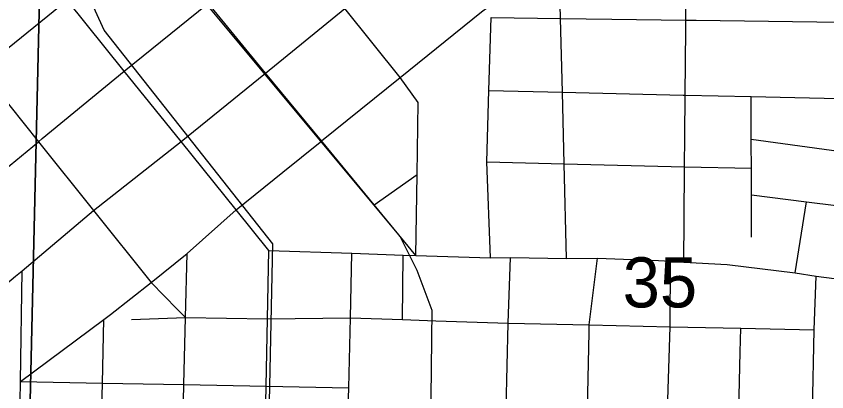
# Model space of a CAD drawing. Extents: x 0 to 68.9, y -26.1 to 22.
# Drawn here: x 5.236 to 5.914, y 17.27 to 17.583 of the extents above; entities that cross this region are included whole.
import ezdxf

# ---------------------------------------------------------------- set-up
doc = ezdxf.new("R2010")
doc.units = 0
for name, color, linetype in [('GM_X_City_Street', 7, 'Continuous'), ('GM_X_Corporation', 7, 'Continuous'), ('GM_X_County_Road', 7, 'Continuous'), ('GM_X_Rail_Line', 7, 'Continuous'), ('GM_X_Section_Text', 7, 'Continuous'), ('GM_X_State_Route', 7, 'Continuous')]:
    doc.layers.add(name, color=color, linetype=linetype)

msp = doc.modelspace()

# ---------------------------------------------------------------- linework, layer by layer
at = {"layer": 'GM_X_City_Street'}
for p, q in [((5.32662, 17.53766), (5.39587, 17.59369)), ((5.25797, 17.48125), (5.32662, 17.53766)), ((5.45913, 17.45315), (5.49028, 17.47824)), ((5.42017, 17.42179), (5.45913, 17.45315)), ((5.53563, 17.42578), (5.57146, 17.45134)), ((5.88774, 17.36892), (5.89704, 17.42847)), ((5.55931, 17.33003), (5.55983, 17.38386)), ((5.33275, 17.32993), (5.37782, 17.33171)), ((5.44643, 17.33069), (5.51568, 17.33143))]:
    msp.add_line(p, q, dxfattribs=at)
for points in [[(5.49028, 17.47824), (5.49153, 17.47925), (5.55726, 17.53218), (5.62538, 17.58703), (5.63051, 17.59116), (5.69013, 17.63916), (5.70842, 17.65389), (5.77503, 17.70506), (5.82165, 17.74087), (5.84893, 17.76184), (5.86765, 17.77621)], [(5.79449, 17.37799), (5.79479, 17.41384), (5.79515, 17.45774), (5.79536, 17.48337), (5.79564, 17.51761), (5.7961, 17.57277), (5.79616, 17.58025), (5.79665, 17.63913), (5.79687, 17.66615), (5.79559, 17.67215), (5.79344, 17.68218), (5.77503, 17.70506)], [(5.69639, 17.38091), (5.69445, 17.46016), (5.69301, 17.51994), (5.69151, 17.58167), (5.69013, 17.63916)], [(5.55726, 17.53218), (5.51093, 17.58994), (5.50776, 17.59389)], [(5.63291, 17.38158), (5.62981, 17.4617), (5.63155, 17.52133), (5.63333, 17.58246)], [(5.63333, 17.58246), (5.69151, 17.58167), (5.7342, 17.58109), (5.79616, 17.58025), (5.80482, 17.58014), (5.92587, 17.57849)], [(5.57052, 17.38348), (5.57146, 17.45134), (5.5723, 17.51136), (5.55726, 17.53218)], [(5.63155, 17.52133), (5.69301, 17.51994), (5.79402, 17.51765), (5.79564, 17.51761), (5.85088, 17.51636), (5.93618, 17.51443)], [(5.85118, 17.39899), (5.85109, 17.43433), (5.85103, 17.4564), (5.85098, 17.47724), (5.85098, 17.48067), (5.85088, 17.51636)], [(5.00502, 17.33155), (5.04003, 17.33297), (5.04422, 17.33314), (5.0795, 17.33458), (5.12537, 17.37228), (5.18817, 17.42389), (5.25474, 17.47859), (5.25797, 17.48125)], [(5.85098, 17.48067), (5.91803, 17.47154), (5.96017, 17.46526), (5.97199, 17.46843)], [(5.62981, 17.4617), (5.69445, 17.46016), (5.79515, 17.45774), (5.85103, 17.4564)], [(5.85109, 17.43433), (5.89704, 17.42847), (5.94466, 17.42241), (6.00736, 17.41442), (6.01916, 17.41376), (6.02679, 17.41435), (6.03512, 17.42217)], [(5.23987, 17.27834), (5.30944, 17.33016), (5.31517, 17.33418), (5.34898, 17.36112), (5.3791, 17.38512), (5.42017, 17.42179)], [(5.35496, 16.38182), (5.35519, 16.39142), (5.35743, 16.48446), (5.35973, 16.58025), (5.36267, 16.70203), (5.36422, 16.76668), (5.36723, 16.8917), (5.36956, 16.9888), (5.3724, 17.10684), (5.37341, 17.14853), (5.37516, 17.22133), (5.37647, 17.27566), (5.37782, 17.33171), (5.3791, 17.38512)], [(5.51075, 17.12816), (5.51218, 17.18711), (5.51296, 17.2194), (5.51384, 17.25548), (5.51426, 17.27296), (5.51568, 17.33143), (5.51698, 17.38537)], [(5.63668, 16.8858), (5.63913, 16.98479), (5.63916, 16.98592), (5.64232, 17.11346), (5.64243, 17.11757), (5.6441, 17.18532), (5.64585, 17.25559), (5.64761, 17.32699), (5.6496, 17.38196)], [(5.71538, 17.3225), (5.71544, 17.32552), (5.72232, 17.38143)], [(5.77674, 17.10959), (5.77877, 17.17846), (5.77894, 17.18444), (5.781, 17.25442), (5.78304, 17.32405), (5.78348, 17.37881)], [(5.22044, 16.39278), (5.22208, 16.48861), (5.22369, 16.58231), (5.22576, 16.70384), (5.22689, 16.76933), (5.22902, 16.8943), (5.22966, 16.93154), (5.23063, 16.98855), (5.23177, 17.05499), (5.23254, 17.10018), (5.2349, 17.11584), (5.23685, 17.12879), (5.23796, 17.13616), (5.23839, 17.16855), (5.23846, 17.17352), (5.23913, 17.22325), (5.23965, 17.26165), (5.23987, 17.27834), (5.24112, 17.37083)], [(5.89423, 16.8799), (5.89759, 17.03731), (5.89885, 17.09664), (5.89918, 17.11222), (5.90069, 17.18363), (5.90072, 17.18488), (5.90218, 17.25338), (5.90363, 17.32143), (5.90525, 17.36624)], [(5.3053, 17.13853), (5.30574, 17.15856), (5.30711, 17.22229), (5.30829, 17.277), (5.30944, 17.33016)], [(5.51568, 17.33143), (5.55931, 17.33003), (5.58702, 17.32908), (5.64761, 17.32699), (5.71544, 17.32552), (5.78304, 17.32405), (5.84215, 17.32277), (5.90363, 17.32143)], [(5.70862, 16.97742), (5.7088, 16.98685), (5.7111, 17.10382), (5.71126, 17.11195), (5.71268, 17.18487), (5.71406, 17.255), (5.71533, 17.31948), (5.71538, 17.3225)], [(5.83724, 17.11351), (5.83888, 17.18326), (5.8389, 17.18404), (5.84053, 17.2539), (5.84168, 17.30284), (5.84215, 17.32277)], [(5.23987, 17.27834), (5.30829, 17.277), (5.37647, 17.27566), (5.44529, 17.27431), (5.51426, 17.27296)]]:
    msp.add_lwpolyline(points, dxfattribs=at)
at = {"layer": 'GM_X_Corporation'}
for points in [[(4.25003, 17.92355), (5.26256, 17.9001), (5.23944, 16.9012), (5.22846, 16.90146), (4.2396, 16.91676)], [(5.26256, 17.9001), (6.27908, 17.8826), (6.25153, 16.877), (5.23944, 16.9012)]]:
    msp.add_lwpolyline(points, close=True, dxfattribs=at)
at = {"layer": 'GM_X_County_Road'}
msp.add_line((5.37413, 17.47882), (5.44471, 17.53602), dxfattribs=at)
for points in [[(5.44471, 17.53602), (5.51093, 17.58994), (5.57872, 17.64515), (5.66023, 17.71152), (5.7246, 17.76393), (5.72634, 17.76535), (5.77147, 17.80169), (5.81437, 17.83622)], [(5.57052, 17.38348), (5.53563, 17.42578), (5.49153, 17.47925), (5.44471, 17.53602), (5.39664, 17.59431), (5.34819, 17.65306)], [(5.20658, 17.53862), (5.25474, 17.47859), (5.30093, 17.42102), (5.34898, 17.36112), (5.37095, 17.33871)], [(5.10584, 17.25734), (5.14647, 17.29144), (5.17263, 17.31338), (5.23556, 17.36617), (5.24112, 17.37083), (5.30093, 17.42102), (5.37413, 17.47882)], [(5.37095, 17.33871), (5.37782, 17.33171), (5.44643, 17.33069)]]:
    msp.add_lwpolyline(points, dxfattribs=at)
at = {"layer": 'GM_X_Rail_Line'}
for points in [[(4.93937, 17.99669), (5.09463, 17.88811), (5.21859, 17.79411), (5.273, 17.74048), (5.55732, 17.3992), (5.57126, 17.37133), (5.58381, 17.3379), (5.58109, 17.09404)], [(5.44504, 17.11606), (5.45083, 17.39325), (5.30989, 17.57185), (5.29533, 17.60396), (5.28697, 17.61092), (5.25632, 17.62902), (5.09325, 17.831), (4.96284, 17.83288)]]:
    msp.add_lwpolyline(points, dxfattribs=at)
at = {"layer": 'GM_X_State_Route'}
msp.add_line((5.44643, 17.33069), (5.44759, 17.38784), dxfattribs=at)
for points in [[(5.08504, 17.44065), (5.13882, 17.484), (5.20658, 17.53862), (5.27882, 17.59686)], [(5.37413, 17.47882), (5.32662, 17.53766), (5.27882, 17.59686)], [(5.44759, 17.38784), (5.42017, 17.42179), (5.37413, 17.47882)], [(5.44759, 17.38784), (5.51698, 17.38537), (5.55983, 17.38386), (5.57052, 17.38348), (5.63291, 17.38158), (5.6496, 17.38196), (5.69639, 17.38091)], [(5.69639, 17.38091), (5.72232, 17.38143), (5.77339, 17.37943), (5.78348, 17.37881), (5.79449, 17.37799), (5.83066, 17.37592), (5.88774, 17.36892), (5.90525, 17.36624), (6.01919, 17.3514), (6.05134, 17.34728), (6.09316, 17.34172), (6.10327, 17.34044)], [(5.44195, 17.11), (5.44253, 17.13828), (5.44419, 17.22036), (5.44529, 17.27431), (5.44643, 17.33069)]]:
    msp.add_lwpolyline(points, dxfattribs=at)

# ---------------------------------------------------------------- texts
at = {"layer": 'GM_X_Section_Text'}
msp.add_text('35', height=0.041856, rotation=0.00001, dxfattribs=at).set_placement((5.74341, 17.34016))

doc.saveas('drawing.dxf')
